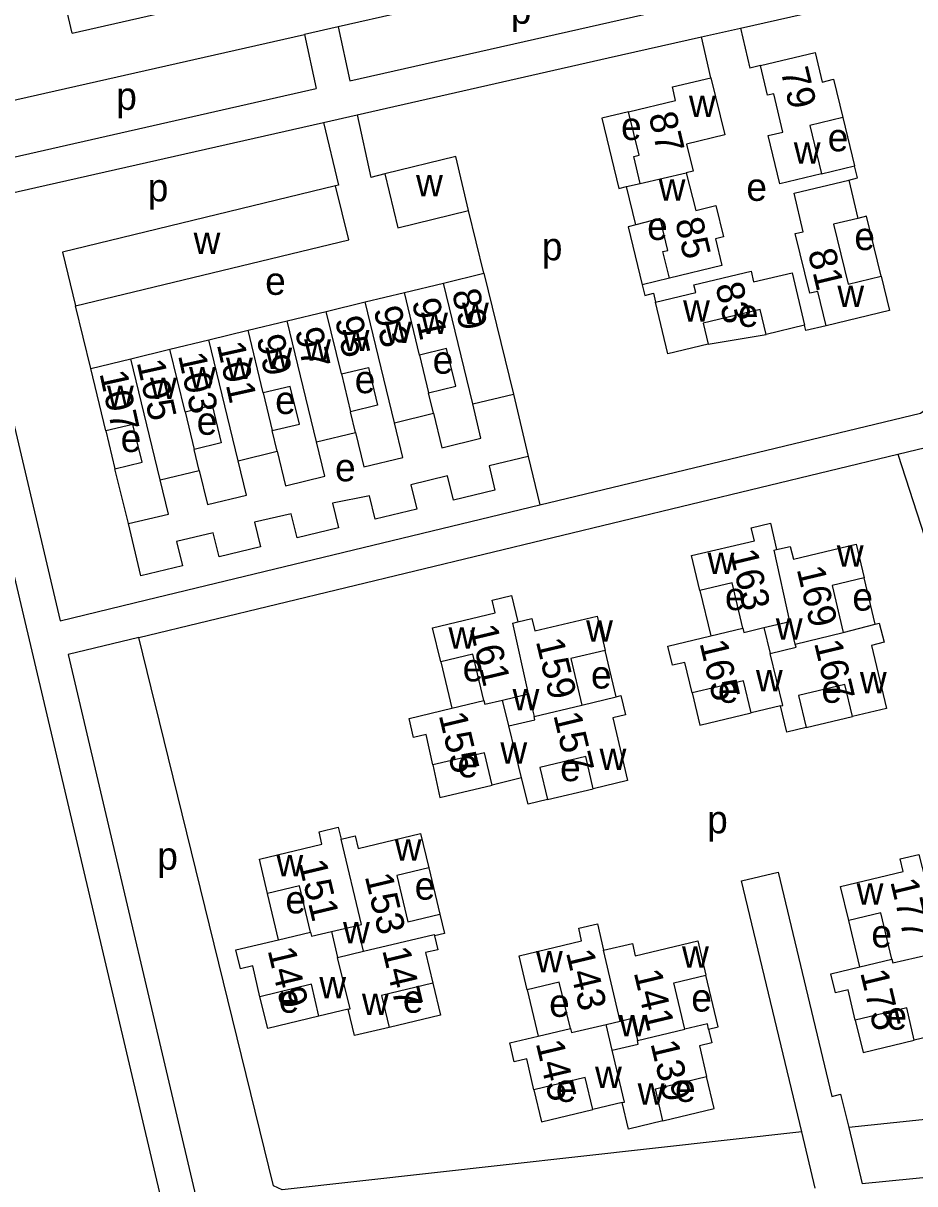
# Model space of a CAD drawing. Extents: x 155854 to 157362, y 383621 to 384685.
# Drawn here: x 156844.9 to 156973.5, y 383930.2 to 384097.6 of the extents above; entities that cross this region are included whole.
import ezdxf

# ---------------------------------------------------------------- set-up
doc = ezdxf.new("R2010")
doc.units = 0
for name, color, linetype in [('BLT_Basislijn', 7, 'Continuous'), ('BLT_Bebouwing', 7, 'Continuous'), ('BLT_Centroide', 7, 'Continuous'), ('BLT_Huisnummer', 7, 'Continuous'), ('BLT_Huisnummer_ tussenligend', 7, 'Continuous'), ('BLT_Onderverdeling_panden', 7, 'Continuous'), ('BLT_Vlakafsluiter', 7, 'Continuous')]:
    doc.layers.add(name, color=color, linetype=linetype)

msp = doc.modelspace()

# ---------------------------------------------------------------- linework, layer by layer
at = {"layer": 'BLT_Basislijn'}
for p, q in [((156851.95, 384096.23), (156847.64, 384114.86)), ((156851.95, 384096.23), (156906.09, 384108.49)), ((156924.98, 384104.97), (156890.35, 384097.12)), ((156892.05, 384089.31), (156952.6, 384103.03)), ((156948.38, 384096.94), (156966.33, 384101.01)), ((156890.35, 384097.12), (156885.47, 384096.03)), ((156890.35, 384097.12), (156892.05, 384089.31)), ((156842.52, 384086.3), (156885.47, 384096.03)), ((156885.47, 384096.03), (156887.17, 384088.21)), ((156929.32, 384092.63), (156942.78, 384095.67)), ((156942.78, 384095.67), (156948.38, 384096.94)), ((156944.12, 384089.78), (156942.78, 384095.67)), ((156948.38, 384096.94), (156949.75, 384091.15)), ((156893.11, 384084.43), (156929.32, 384092.63)), ((156951.27, 384091.52), (156949.75, 384091.15)), ((156810.79, 384070.91), (156887.17, 384088.21)), ((156888.24, 384083.32), (156893.11, 384084.43)), ((156893.11, 384084.43), (156895.08, 384075.4)), ((156963.16, 384084.03), (156964.85, 384077.06)), ((156836.07, 384071.51), (156888.24, 384083.32)), ((156960.08, 384075.91), (156964.85, 384077.06)), ((156897.06, 384075.91), (156895.08, 384075.4)), ((156831.19, 384070.4), (156867.7, 383915.55)), ((156911.36, 384061.57), (156909.17, 384070.63)), ((156938.14, 384060.86), (156934.22, 384059.91)), ((156854.65, 384047.84), (156852.46, 384056.86)), ((156943.75, 384051.34), (156952.11, 384052.74)), ((156915.63, 384044.14), (156917.76, 384035.15)), ((156856.83, 384038.81), (156858.15, 384033.36)), ((156861.89, 384017.92), (156860.1, 384025.44)), ((156967.81, 384010.93), (156966.23, 384017.6)), ((156942.53, 384015.79), (156944.09, 384009.24)), ((156863.37, 384001.73), (156861.58, 384009.03)), ((156930.46, 384000.47), (156928.89, 384007.13)), ((156905.17, 384005.49), (156906.74, 383998.8)), ((156864.57, 383996.87), (156863.37, 384001.73)), ((156957.86, 383996.02), (156964.54, 383997.61)), ((156920.54, 383985.62), (156927.14, 383987.19)), ((156903.43, 383975.78), (156905, 383969.1)), ((156881.76, 383965.4), (156880.17, 383972.08)), ((156965.6, 383961.48), (156964.01, 383968.18)), ((156917.61, 383958.18), (156919.21, 383951.51)), ((156964, 383938.3), (156965.94, 383930.2)), ((156959.19, 383929.54), (156957.23, 383937.68))]:
    msp.add_line(p, q, dxfattribs=at)
for points in [[(156932.25, 384084.86), (156928.41, 384083.94), (156930.86, 384073.8), (156931.97, 384074.07)], [(156888.24, 384083.32), (156890.41, 384074.27), (156889.98, 384074.17)], [(156964.01, 384075.02), (156965.27, 384075.32), (156964.85, 384077.06)], [(156836.07, 384071.51), (156850.23, 384011.44), (156862.71, 384014.45)], [(156933.3, 384068.55), (156932.2, 384068.26), (156934.22, 384059.91)], [(156968.67, 384061.16), (156966.59, 384069.78), (156965.34, 384069.48)], [(156934.22, 384059.91), (156934.59, 384058.37), (156935.82, 384058.67), (156936.13, 384057.41)], [(156919.42, 384028.13), (156974.36, 384041.38), (156996.13, 384056.85)], [(156960.74, 384054), (156957.84, 384053.3), (156957.65, 384054.07)], [(156971.1, 384035.45), (156976.47, 384036.75), (156979.26, 384038.73)], [(156861.58, 384009.03), (156971.1, 384035.45)], [(156917.76, 384035.15), (156912.12, 384033.78), (156912.96, 384030.28), (156906.97, 384028.84), (156906.13, 384032.32), (156900.84, 384031.05), (156901.68, 384027.55), (156895.7, 384026.1), (156894.89, 384029.47), (156889.55, 384028.39), (156890.42, 384024.83), (156884.42, 384023.37), (156883.57, 384026.86), (156878.29, 384025.65), (156879.15, 384022.08), (156873.16, 384020.64), (156872.3, 384024.12), (156867.03, 384022.85), (156867.88, 384019.35), (156861.89, 384017.92)], [(156971.1, 384035.45), (157001.27, 383942.23), (156964, 383938.3)], [(156862.71, 384014.45), (156919.42, 384028.13)], [(156861.58, 384009.03), (156851.38, 384006.57), (156871.56, 383920.95)], [(156941.43, 384001.01), (156942.53, 383996.38), (156949.93, 383998.14)], [(156957.23, 383937.68), (156882.29, 383929.3), (156881.04, 383929.91), (156864.57, 383996.87)], [(156904.02, 383990.64), (156905.04, 383985.95), (156912.55, 383987.71)], [(156957.23, 383937.68), (156948.54, 383973.88), (156953.81, 383975.15), (156961.55, 383942.81), (156962.84, 383943.12), (156964, 383938.3)], [(156943.79, 383952.52), (156945.18, 383952.85), (156943.41, 383960.29)], [(156904, 383959.15), (156905.11, 383954.51), (156897.73, 383952.76)], [(156887.58, 383954.36), (156880.19, 383952.58), (156879.05, 383957.15)], [(156964.96, 383953.81), (156966.08, 383949.14), (156973.47, 383950.93)], [(156937.2, 383939.28), (156944.6, 383941.04), (156943.51, 383945.67)], [(156918.58, 383943.75), (156919.7, 383939.12), (156927.09, 383940.9)], [(157003.96, 383933.92), (156965.94, 383930.2)]]:
    msp.add_lwpolyline(points, dxfattribs=at)
at = {"layer": 'BLT_Bebouwing'}
for p, q in [((156931.97, 384074.07), (156933.91, 384074.54)), ((156933.3, 384068.55), (156931.97, 384074.07)), ((156964.01, 384075.02), (156965.34, 384069.48)), ((156905.54, 384060.16), (156911.36, 384061.57)), ((156894.26, 384057.43), (156899.9, 384058.8)), ((156899.9, 384058.8), (156905.54, 384060.16)), ((156888.62, 384056.07), (156894.26, 384057.43)), ((156882.98, 384054.7), (156888.62, 384056.07)), ((156877.35, 384053.34), (156882.98, 384054.7)), ((156957.65, 384054.07), (156952.11, 384052.74)), ((156866.07, 384050.6), (156871.71, 384051.97)), ((156871.71, 384051.97), (156877.35, 384053.34)), ((156860.43, 384049.24), (156866.07, 384050.6)), ((156856.83, 384038.81), (156854.65, 384047.84)), ((156890.81, 384047.04), (156892.12, 384041.59)), ((156879.53, 384044.31), (156880.85, 384038.86)), ((156909.76, 384042.71), (156915.63, 384044.14)), ((156868.26, 384041.58), (156869.58, 384036.13)), ((156898.48, 384039.97), (156904.12, 384041.36)), ((156887.21, 384037.23), (156892.85, 384038.59)), ((156875.94, 384034.51), (156881.57, 384035.88)), ((156860.1, 384025.44), (156858.15, 384033.36)), ((156864.68, 384031.75), (156870.31, 384033.12))]:
    msp.add_line(p, q, dxfattribs=at)
for points in [[(156951.27, 384091.52), (156959.16, 384093.43), (156960.2, 384089.16), (156961.83, 384089.55), (156963.16, 384084.03)], [(156960.08, 384075.91), (156954.06, 384074.45), (156952.38, 384081.43), (156954.52, 384081.94), (156953.18, 384087.45), (156952.31, 384087.24), (156951.27, 384091.52)], [(156932.25, 384084.86), (156939.04, 384086.5), (156938.57, 384088.44), (156944.12, 384089.78)], [(156944.12, 384089.78), (156946.12, 384081.53), (156940.61, 384080.19), (156941.56, 384076.31), (156940.57, 384076.07)], [(156933.91, 384074.54), (156932.99, 384078.39), (156933.77, 384078.59), (156932.25, 384084.86)], [(156963.16, 384084.03), (156958.41, 384082.88), (156960.08, 384075.91)], [(156909.17, 384070.63), (156907.31, 384078.4), (156897.06, 384075.91)], [(156897.06, 384075.91), (156898.94, 384068.13), (156909.17, 384070.63)], [(156940.57, 384076.07), (156941.94, 384070.62), (156944.85, 384071.35), (156945.95, 384066.82), (156944.8, 384066.55), (156945.72, 384062.7), (156938.14, 384060.86)], [(156889.98, 384074.17), (156850.57, 384064.62), (156852.46, 384056.86)], [(156852.46, 384056.86), (156891.87, 384066.41), (156889.98, 384074.17)], [(156960.74, 384054), (156959.55, 384058.95), (156958.38, 384058.67), (156956.3, 384067.29), (156957.45, 384067.56), (156956.12, 384073.11), (156964.01, 384075.02)], [(156938.14, 384060.86), (156937.21, 384064.69), (156937.91, 384064.86), (156936.79, 384069.46), (156933.3, 384068.55)], [(156965.34, 384069.48), (156961.83, 384068.63), (156963.92, 384060.01), (156968.67, 384061.16)], [(156936.13, 384057.41), (156941.93, 384058.81), (156941.68, 384059.88), (156949.91, 384061.87), (156950.28, 384060.32), (156955.83, 384061.64), (156957.65, 384054.07)], [(156911.36, 384061.57), (156915.63, 384044.14)], [(156968.67, 384061.16), (156969.87, 384056.2), (156960.74, 384054)], [(156943.75, 384051.34), (156937.93, 384049.95), (156936.13, 384057.41)], [(156952.11, 384052.74), (156951.24, 384056.34), (156943.02, 384054.35), (156943.75, 384051.34)], [(156903.4, 384044.32), (156907.31, 384045.27), (156905.99, 384050.71), (156902.08, 384049.77)], [(156854.65, 384047.84), (156860.43, 384049.24)], [(156902.08, 384049.77), (156903.4, 384044.32), (156903.4, 384044.32)], [(156890.81, 384047.04), (156894.71, 384047.98), (156896.03, 384042.54), (156892.12, 384041.59)], [(156880.85, 384038.86), (156884.75, 384039.81), (156883.43, 384045.25), (156879.53, 384044.31)], [(156868.26, 384041.58), (156872.16, 384042.52), (156873.48, 384037.08), (156869.58, 384036.13)], [(156904.12, 384041.36), (156905.32, 384036.4), (156910.95, 384037.76), (156909.76, 384042.71)], [(156858.15, 384033.36), (156862.06, 384034.31), (156860.74, 384039.75), (156856.83, 384038.81)], [(156892.85, 384038.59), (156894.05, 384033.65), (156899.69, 384035), (156898.48, 384039.97)], [(156881.57, 384035.88), (156882.77, 384030.91), (156888.41, 384032.29), (156887.21, 384037.23)], [(156870.31, 384033.12), (156871.5, 384028.19), (156877.14, 384029.56), (156875.94, 384034.51)], [(156860.1, 384025.44), (156865.87, 384026.82), (156864.68, 384031.75)], [(156942.53, 384015.79), (156941.34, 384020.83), (156950.39, 384022.97), (156949.95, 384024.83), (156952.72, 384025.49), (156953.57, 384021.69)], [(156953.57, 384021.69), (156955.58, 384022.16), (156956.02, 384020.33), (156965.07, 384022.48), (156966.23, 384017.6)], [(156948.74, 384010.35), (156947.19, 384016.9), (156942.53, 384015.79)], [(156966.23, 384017.6), (156961.6, 384016.5), (156963.22, 384009.71)], [(156905.17, 384005.49), (156903.98, 384010.43), (156913.01, 384012.58), (156912.59, 384014.4), (156915.36, 384015.06), (156916.27, 384011.27)], [(156916.27, 384011.27), (156918.28, 384011.75), (156918.71, 384009.95), (156927.72, 384012.08), (156928.89, 384007.13)], [(156944.09, 384009.24), (156948.74, 384010.35)], [(156963.22, 384009.71), (156967.81, 384010.93)], [(156967.81, 384010.93), (156968.38, 384011.08), (156969.12, 384008.33), (156967.29, 384007.84), (156969.47, 383998.79), (156964.54, 383997.61)], [(156941.43, 384001.01), (156940.38, 384005.41), (156938.56, 384005.01), (156937.9, 384007.77), (156944.09, 384009.24)], [(156928.89, 384007.13), (156923.93, 384005.96), (156925.52, 383999.26)], [(156911.37, 383999.9), (156909.8, 384006.59), (156905.17, 384005.49)], [(156949.93, 383998.14), (156948.81, 384002.76), (156941.43, 384001.01)], [(156964.54, 383997.61), (156963.43, 384002.24), (156956.74, 384000.64), (156957.86, 383996.02)], [(156906.74, 383998.8), (156911.37, 383999.9)], [(156925.52, 383999.26), (156930.46, 384000.47)], [(156930.46, 384000.47), (156931.11, 384000.63), (156931.78, 383997.86), (156929.97, 383997.4), (156932.11, 383988.39), (156927.14, 383987.19)], [(156904.02, 383990.64), (156903.06, 383995.02), (156901.23, 383994.56), (156900.57, 383997.34), (156906.74, 383998.8)], [(156954.15, 383999.13), (156949.93, 383998.14)], [(156957.86, 383996.02), (156955.07, 383995.35), (156954.15, 383999.13)], [(156912.55, 383987.71), (156911.45, 383992.38), (156904.02, 383990.64)], [(156927.14, 383987.19), (156926.08, 383991.83), (156919.43, 383990.24), (156920.54, 383985.62)], [(156916.82, 383988.76), (156912.55, 383987.71)], [(156920.54, 383985.62), (156917.75, 383984.95), (156916.82, 383988.76)], [(156880.17, 383972.08), (156878.99, 383977.02), (156888, 383979.18), (156887.59, 383980.99), (156890.35, 383981.65), (156890.77, 383979.9)], [(156890.77, 383979.9), (156892.79, 383980.39), (156893.23, 383978.56), (156902.25, 383980.73), (156903.43, 383975.78)], [(156964.01, 383968.18), (156962.83, 383973.11), (156971.85, 383975.26), (156971.42, 383977.06), (156974.14, 383977.72), (156975.06, 383973.93)], [(156903.43, 383975.78), (156898.81, 383974.68), (156900.38, 383968.01), (156905, 383969.1)], [(156886.37, 383966.51), (156884.79, 383973.19), (156880.17, 383972.08)], [(156905, 383969.1), (156905.67, 383966.3), (156904.27, 383965.97)], [(156970.23, 383962.6), (156968.63, 383969.3), (156964.01, 383968.18)], [(156881.76, 383965.4), (156886.37, 383966.51)], [(156917.61, 383958.18), (156916.44, 383963.09), (156925.47, 383965.24), (156925.06, 383967.06), (156927.77, 383967.69), (156928.65, 383963.89)], [(156879.05, 383957.15), (156878.06, 383961.62), (156876.24, 383961.2), (156875.59, 383963.93), (156881.76, 383965.4)], [(156904.27, 383965.97), (156904.75, 383963.96), (156902.96, 383963.55), (156904, 383959.15)], [(156928.65, 383963.89), (156932.79, 383964.88), (156933.22, 383963.07), (156942.23, 383965.23), (156943.41, 383960.29)], [(156964.96, 383953.81), (156963.92, 383958.16), (156962.1, 383957.73), (156961.45, 383960.5), (156965.6, 383961.48)], [(156965.6, 383961.48), (156970.23, 383962.6)], [(156940.37, 383952.49), (156938.79, 383959.19), (156943.41, 383960.29)], [(156887.58, 383954.36), (156886.48, 383958.98), (156879.05, 383957.15)], [(156904, 383959.15), (156896.6, 383957.37), (156897.73, 383952.76)], [(156923.85, 383952.6), (156922.24, 383959.27), (156917.61, 383958.18)], [(156891.79, 383955.37), (156887.58, 383954.36)], [(156897.73, 383952.76), (156892.72, 383951.57), (156891.79, 383955.37)], [(156973.47, 383950.93), (156972.37, 383955.6), (156964.96, 383953.81)], [(156943.79, 383952.52), (156943.61, 383953.26), (156940.37, 383952.49)], [(156918.58, 383943.75), (156917.55, 383948.21), (156915.75, 383947.78), (156915.1, 383950.55), (156919.21, 383951.51)], [(156919.21, 383951.51), (156923.85, 383952.6)], [(156943.79, 383952.52), (156944.27, 383950.51), (156942.46, 383950.08), (156943.51, 383945.67)], [(156977.7, 383951.93), (156973.47, 383950.93)], [(156927.09, 383940.9), (156925.97, 383945.52), (156918.58, 383943.75)], [(156937.2, 383939.28), (156936.11, 383943.91), (156943.51, 383945.67)], [(156931.32, 383941.9), (156927.09, 383940.9)], [(156937.2, 383939.28), (156932.22, 383938.09), (156931.32, 383941.9)]]:
    msp.add_lwpolyline(points, dxfattribs=at)
at = {"layer": 'BLT_Onderverdeling_panden'}
for p, q in [((156933.91, 384074.54), (156940.57, 384076.07)), ((156902.08, 384049.77), (156899.9, 384058.8)), ((156890.81, 384047.04), (156888.62, 384056.07)), ((156879.53, 384044.31), (156877.35, 384053.34)), ((156868.26, 384041.58), (156866.07, 384050.6)), ((156904.12, 384041.36), (156903.4, 384044.32)), ((156892.85, 384038.59), (156892.12, 384041.59)), ((156881.57, 384035.88), (156880.85, 384038.86)), ((156870.31, 384033.12), (156869.58, 384036.13)), ((156953.24, 384021.61), (156953.57, 384021.69)), ((156955.53, 384011.33), (156953.24, 384021.61)), ((156915.55, 384011.1), (156916.27, 384011.27)), ((156917.83, 384000.88), (156915.55, 384011.1)), ((156948.74, 384010.35), (156948.89, 384009.75)), ((156948.89, 384009.75), (156951.77, 384010.44)), ((156951.77, 384010.44), (156955.53, 384011.33)), ((156951.77, 384010.44), (156952.65, 384006.71)), ((156956.3, 384008.06), (156955.53, 384011.33)), ((156956.3, 384008.06), (156963.22, 384009.71)), ((156952.65, 384006.71), (156956.41, 384007.6)), ((156954.48, 383999.21), (156952.65, 384006.71)), ((156956.41, 384007.6), (156956.3, 384008.06)), ((156911.37, 383999.9), (156911.5, 383999.38)), ((156911.5, 383999.38), (156914.07, 383999.99)), ((156914.07, 383999.99), (156917.83, 384000.88)), ((156914.95, 383996.26), (156914.07, 383999.99)), ((156917.83, 384000.88), (156918.61, 383997.62)), ((156918.61, 383997.62), (156925.52, 383999.26)), ((156954.15, 383999.13), (156954.48, 383999.21)), ((156914.95, 383996.26), (156918.72, 383997.15)), ((156918.72, 383997.15), (156918.61, 383997.62)), ((156916.82, 383988.76), (156914.95, 383996.26)), ((156893.71, 383967.62), (156890.77, 383979.9)), ((156886.37, 383966.51), (156886.51, 383965.91)), ((156886.51, 383965.91), (156889.38, 383966.59)), ((156889.38, 383966.59), (156893.14, 383967.48)), ((156889.38, 383966.59), (156890.26, 383962.86)), ((156893.14, 383967.48), (156893.71, 383967.62)), ((156894.02, 383963.75), (156893.14, 383967.48)), ((156894.02, 383963.75), (156904.22, 383966.16)), ((156904.22, 383966.16), (156904.27, 383965.97)), ((156890.26, 383962.86), (156894.02, 383963.75)), ((156931.04, 383953.67), (156928.65, 383963.89)), ((156970.37, 383962.05), (156975.41, 383963.23)), ((156892.07, 383955.44), (156890.26, 383962.86)), ((156970.23, 383962.6), (156970.37, 383962.05)), ((156891.79, 383955.37), (156892.07, 383955.44)), ((156923.99, 383952.02), (156929, 383953.19)), ((156929, 383953.19), (156931.04, 383953.67)), ((156929.88, 383949.46), (156929, 383953.19)), ((156931.04, 383953.67), (156932.77, 383954.08)), ((156932.77, 383954.08), (156933.53, 383950.86)), ((156923.85, 383952.6), (156923.99, 383952.02)), ((156933.53, 383950.86), (156940.37, 383952.49)), ((156929.88, 383949.46), (156933.65, 383950.35)), ((156933.65, 383950.35), (156933.53, 383950.86)), ((156931.66, 383941.98), (156929.88, 383949.46)), ((156931.32, 383941.9), (156931.66, 383941.98))]:
    msp.add_line(p, q, dxfattribs=at)
for points in [[(156909.76, 384042.71), (156905.54, 384060.16)], [(156898.48, 384039.97), (156894.26, 384057.43)], [(156887.21, 384037.23), (156882.98, 384054.7)], [(156875.94, 384034.51), (156871.71, 384051.97)], [(156864.68, 384031.75), (156860.43, 384049.24)]]:
    msp.add_lwpolyline(points, dxfattribs=at)
at = {"layer": 'BLT_Vlakafsluiter'}
msp.add_line((156917.76, 384035.15), (156919.42, 384028.13), dxfattribs=at)

# ---------------------------------------------------------------- texts
at = {"layer": 'BLT_Centroide'}
for s, p in [('p', (156915.25, 384097.57)), ('p', (156858.33, 384085.14)), ('w', (156940.96, 384084.1)), ('e', (156931.16, 384080.8)), ('e', (156960.98, 384079.16)), ('w', (156956.08, 384077.39)), ('w', (156901.59, 384072.67)), ('p', (156862.88, 384071.93)), ('w', (156936.59, 384072.06)), ('e', (156949.24, 384072.01)), ('e', (156934.93, 384066.37)), ('w', (156869.49, 384064.36)), ('e', (156964.82, 384064.91)), ('p', (156919.73, 384063.44)), ('e', (156879.82, 384058.45)), ('w', (156962.37, 384056.72)), ('w', (156908.22, 384054.26)), ('w', (156940.11, 384054.59)), ('e', (156948.02, 384053.83)), ('w', (156902.32, 384052.81)), ('w', (156897.1, 384051.52)), ('w', (156885.44, 384048.94)), ('w', (156891, 384050.33)), ('w', (156879.85, 384047.75)), ('e', (156903.98, 384047.07)), ('w', (156874.17, 384046.3)), ('w', (156868.84, 384044.96)), ('e', (156892.74, 384044.26)), ('w', (156857, 384042.27)), ('w', (156863.2, 384043.41)), ('e', (156881.26, 384041.26)), ('e', (156869.94, 384038.26)), ('e', (156858.97, 384035.78)), ('e', (156889.9, 384031.55)), ('w', (156962.29, 384019.24)), ('w', (156943.64, 384018.19)), ('e', (156946.15, 384012.96)), ('e', (156964.53, 384012.89)), ('w', (156953.49, 384008.69)), ('w', (156906.26, 384007.42)), ('w', (156926.12, 384008.42)), ('e', (156908.31, 384002.68)), ('e', (156926.82, 384001.65)), ('w', (156950.62, 384001.25)), ('w', (156965.62, 384000.96)), ('w', (156915.51, 383998.51)), ('e', (156945.13, 383999.59)), ('e', (156960.07, 383999.59)), ('w', (156913.75, 383990.8)), ('e', (156907.56, 383988.83)), ('w', (156928.06, 383989.9)), ('e', (156922.37, 383988.28)), ('p', (156943.58, 383980.76)), ('w', (156898.52, 383976.83)), ('p', (156864.25, 383975.51)), ('w', (156881.44, 383974.57)), ('e', (156901.39, 383971.19)), ('w', (156965.15, 383970.47)), ('e', (156882.74, 383969.2)), ('w', (156891.05, 383964.89)), ('e', (156967.27, 383964.29)), ('w', (156918.88, 383960.69)), ('w', (156939.96, 383961.36)), ('w', (156887.63, 383956.97)), ('e', (156941.29, 383955.04)), ('e', (156881.78, 383954.87)), ('w', (156893.78, 383954.56)), ('e', (156899.68, 383954.87)), ('e', (156920.79, 383954.28)), ('e', (156969.46, 383952.43)), ('w', (156930.88, 383951.46)), ('w', (156927.41, 383944.02)), ('e', (156921.75, 383942.01)), ('w', (156933.56, 383941.6)), ('e', (156938.96, 383942.01))]:
    msp.add_text(s, height=4, dxfattribs=at).set_placement(p)
at = {"layer": 'BLT_Huisnummer'}
for s, rotation, p in [('79', 283.4988, (156954.16, 384090.79)), ('87', 283.4988, (156935.1, 384084.37)), ('85', 283.4988, (156938.92, 384069.14)), ('81', 283.4988, (156958.08, 384064.64)), ('83', 283.4988, (156944.73, 384059.8)), ('89', 282.4988, (156906.75, 384058.89)), ('93', 282.4988, (156895.44, 384056.39)), ('97', 282.4988, (156884.1, 384053.32)), ('101', 282.4988, (156872.83, 384051.3)), ('107', 282.4988, (156855.89, 384047.13)), ('163', 283.4471, (156946.81, 384021.3)), ('169', 283.4471, (156956.48, 384018.89)), ('161', 283.4471, (156909.3, 384010.42)), ('159', 283.4471, (156918.85, 384008.48)), ('165', 283.4471, (156942.46, 384008.23)), ('167', 283.4471, (156958.99, 384008.24)), ('155', 283.4471, (156904.84, 383997.82)), ('157', 283.4471, (156921.37, 383997.83)), ('151', 283.4471, (156884.61, 383976.51)), ('153', 283.4471, (156894.17, 383974.56)), ('177', 283.4471, (156969.98, 383973.81)), ('149', 283.4471, (156880.15, 383963.9)), ('147', 283.4471, (156896.68, 383963.92)), ('143', 283.4471, (156923.19, 383963.57)), ('141', 283.4471, (156932.97, 383960.69)), ('175', 283.4471, (156965.64, 383960.68)), ('145', 283.4471, (156918.84, 383950.5)), ('139', 283.4471, (156935.38, 383950.46))]:
    msp.add_text(s, height=4, rotation=rotation, dxfattribs=at).set_placement(p)
at = {"layer": 'BLT_Huisnummer_ tussenligend'}
for s, p in [('91', (156900.96, 384057.53)), ('95', (156889.86, 384054.95)), ('99', (156878.55, 384052.3)), ('105', (156861.27, 384048.74)), ('103', (156867.23, 384049.73))]:
    msp.add_text(s, height=4, rotation=282.4988, dxfattribs=at).set_placement(p)

doc.saveas('drawing.dxf')
